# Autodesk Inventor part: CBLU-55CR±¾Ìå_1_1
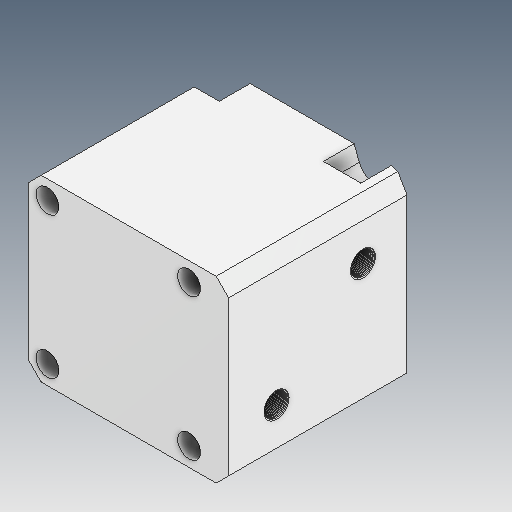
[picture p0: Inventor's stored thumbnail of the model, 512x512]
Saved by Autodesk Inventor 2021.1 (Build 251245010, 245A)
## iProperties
Created: 2021-05
Part Number: CBLU-55CR±¾Ìå_1_1
Material: Ogólny
Document SubType Name: Modeling
Designer: user
Density: 1 g/cm^3
Appearance: Domyślna
Author: user
Revision Number: ÈÎºÎ
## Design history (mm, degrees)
feature "ÊäÈë1"
feature "ÊäÈë2"
feature "ÊäÈë3"
feature "ÊäÈë4"
node "Bryła1"
node "Bryła2"
node "Bryła3"
node "Bryła4"
